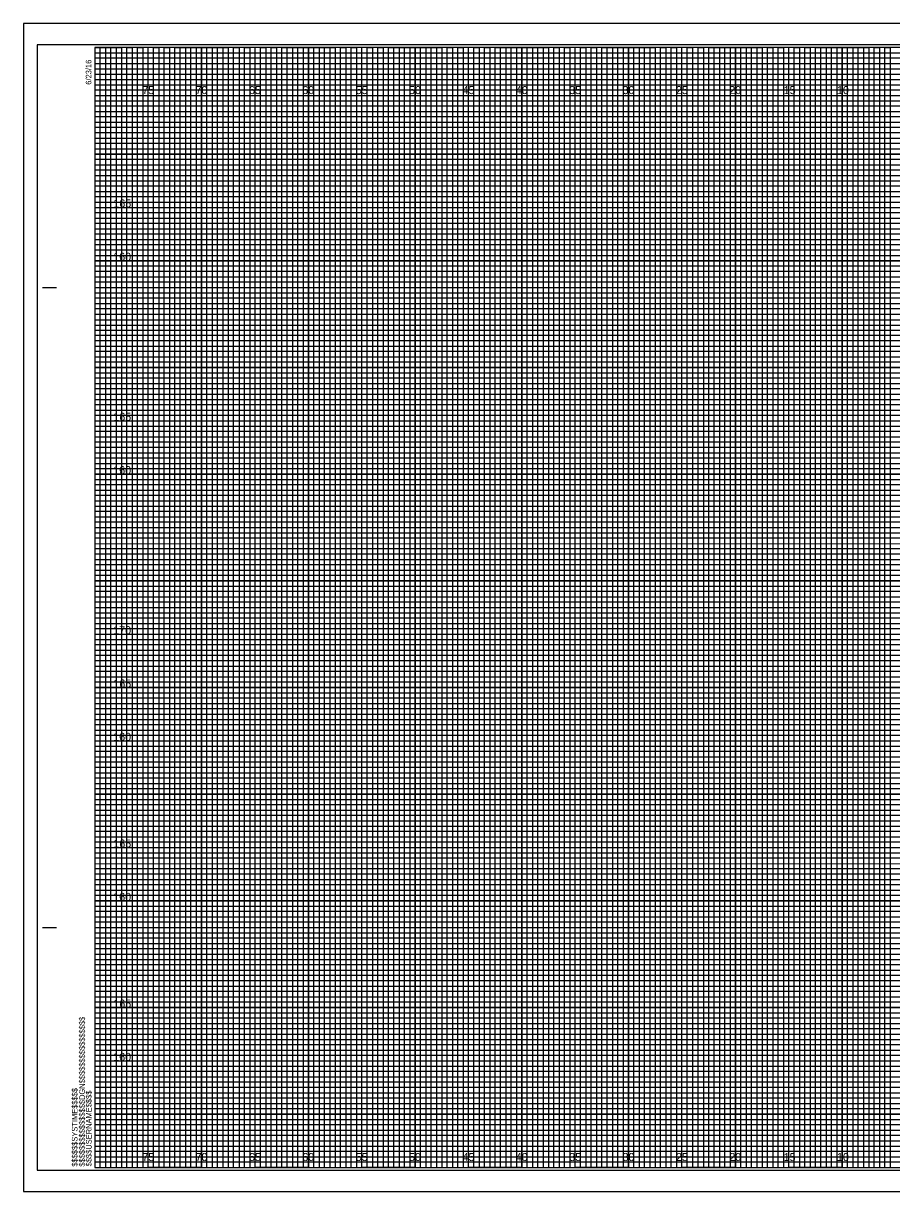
# Model space of a CAD drawing. Extents: x -7 to 162, y -2 to 107.
# Drawn here: x -6.7 to 74.6, y -2.3 to 107.3 of the extents above; entities that cross this region are included whole.
import ezdxf

# ---------------------------------------------------------------- set-up
doc = ezdxf.new("R2010")
doc.units = 0
for name, color, linetype in [('Exist CMT Pavement', 7, 'Continuous'), ('Prop CMT Pvmt Course 1 Wedge', 7, 'Continuous'), ('Prop CMT Pvmt Course 2 Wedge', 7, 'Continuous'), ('Prop CMT Pvmt Course 3 Wedge', 7, 'Continuous'), ('Prop CMT Pvmt Wedge Surface 1', 7, 'Continuous'), ('Prop CMT Pvmt Wedge Surface 2', 7, 'Continuous'), ('Prop XS Ditch Standard Text', 7, 'Continuous'), ('Prop XS Earthwork Shape', 7, 'Continuous'), ('Prop XS Hydro Elevations', 7, 'Continuous'), ('Prop XS SE Text', 7, 'Continuous'), ('Prop XS Side Slope Text', 7, 'Continuous')]:
    doc.layers.add(name, color=color, linetype=linetype)

msp = doc.modelspace()

# ---------------------------------------------------------------- linework, layer by layer
at = {"layer": 'Exist CMT Pavement'}
for p, q in [((0, 104.5), (130, 104.5)), ((130, 103.99), (0, 103.99)), ((0, 103.99), (0, 103.5)), ((0, 103.5), (130, 103.5)), ((130, 102.95), (0, 102.95)), ((0, 102.95), (0, 102)), ((0, 102), (160, 102))]:
    msp.add_line(p, q, dxfattribs=at)
for points in [[(0, 101.5), (135, 101.5), (160, 101.5), (160, 101), (0, 101)], [(0, 100.5), (160, 100.5), (160, 99.5), (0, 99.5)], [(0, 99), (160, 99), (160, 98.5), (0, 98.49)], [(0, 98), (160, 98), (160, 97), (0, 97)], [(0, 96.5), (160, 96.5), (160, 96), (0, 96)], [(0, 95.5), (160, 95.5), (160, 94.5), (0, 94.5)], [(0, 94), (160, 94), (160, 93.5), (0, 93.5)], [(0, 93), (160, 93), (160, 92), (0, 92)], [(0, 91.5), (160, 91.5), (160, 91), (0, 91)], [(0, 90.5), (160, 90.5), (160, 89.5), (0, 89.5)], [(0, 89), (160, 89), (160, 88.5), (0, 88.5)], [(0, 88), (160, 88), (160, 86.98), (160, 86.5), (160, 86), (0, 86)], [(0, 87), (160, 87), (160, 86.5), (0, 86.5)], [(0, 85.5), (160, 85.5), (160, 84.5), (0, 84.52)], [(0, 84.52), (160, 84.5), (160, 84), (0, 84)], [(0, 83.5), (160, 83.5), (160, 83), (0, 83)], [(0, 82), (160, 82), (160, 81.5), (0, 81.5)], [(0, 81), (160, 81), (160, 80.5), (0, 80.5)], [(-0.04, 79.45), (160, 79.45), (160, 78.94), (-0.04, 78.94)], [(0, 78.5), (160, 78.5), (160, 78), (0, 78)], [(0, 77), (160, 77), (160, 76.5), (0, 76.5)], [(0, 76), (160, 76), (160, 75.5), (0, 75.5)], [(0, 74.5), (160, 74.5), (160, 74), (0, 74)], [(0, 73.5), (160, 73.5), (160, 73), (0, 73)], [(0, 72), (160, 72), (160, 71.5), (0, 71.5)], [(0, 71), (160, 71), (160, 70.5), (0, 70.5)], [(0, 69.5), (160, 69.5), (160, 68.99), (0, 69)], [(0, 68.5), (160, 68.5), (160, 68), (0, 68)], [(0, 67), (160, 67), (160, 66.5), (0, 66.5)], [(0, 66), (160, 66), (160, 65.5), (0, 65.5)], [(0, 64.5), (160, 64.5), (160, 64), (0, 64)], [(0, 63.5), (160, 63.5), (160, 63), (0, 63)], [(0, 62), (160, 62), (160, 61.5), (0, 61.5)], [(0, 61), (160, 61), (160, 60.5), (0, 60.5)], [(0, 59.5), (160, 59.5), (160, 59), (0, 59)], [(0, 58.5), (160.03, 58.45), (160, 58), (0, 58)], [(0, 57), (160, 57), (160, 56.5), (0, 56.5)], [(0, 56), (160, 56), (160, 55.5), (0, 55.5)], [(0, 54.5), (160, 54.5), (160, 54), (0, 54)], [(0, 53.5), (160, 53.5), (160, 53), (0, 53)], [(0, 52), (160, 52), (160, 51.5), (0, 51.5)], [(0, 51), (160, 51), (160, 50.5), (0, 50.5)], [(0, 49.5), (160, 49.5), (160, 49), (0, 49)], [(0, 48.5), (160, 48.5), (160, 48), (0, 48)], [(0, 47), (160, 47), (160, 46.5), (0, 46.5)], [(0, 46), (160, 46), (160, 45.5), (0, 45.5)], [(0, 44.5), (160, 44.5), (160, 44), (0, 44)], [(0, 43.5), (160, 43.5), (160, 43), (0, 43)], [(0, 42), (160, 42), (160, 41.5), (0, 41.5)], [(0, 41), (160, 41), (160, 40.5), (0, 40.5)], [(0, 39.5), (160, 39.5), (160, 38.99), (0, 39)], [(0, 38.5), (160, 38.5), (160, 38), (0, 38)], [(0, 37), (160, 37), (160, 36.5), (0, 36.5)], [(0, 36), (160, 36), (160, 35.5), (0, 35.5)], [(0, 34.5), (160, 34.5), (160, 34), (0, 34)], [(0, 33.5), (160, 33.5), (160, 33), (0, 33)], [(0, 32), (160, 32), (160, 31.5), (0, 31.5)], [(0, 31), (160, 31), (160, 30.5), (0, 30.5)], [(0, 29.5), (160, 29.5), (160, 29), (0, 29)], [(0, 28.5), (160.03, 28.46), (160, 28), (0, 28)], [(0, 27), (160, 27), (160, 26.5), (0, 26.5)], [(0, 26), (160, 26), (160, 25.5), (0, 25.5)], [(0, 24.5), (160, 24.5), (160, 24), (0, 24)], [(0, 23.5), (160, 23.5), (160, 23), (0, 23)], [(0, 22), (160, 22), (160, 21.5), (0, 21.5)], [(0, 21), (160, 21), (160, 20.5), (0, 20.5)], [(0, 19.5), (160, 19.5), (160, 19), (0, 19)], [(0, 18.5), (160, 18.5), (160, 18), (0, 18)], [(0, 17), (160, 17), (160, 16.5), (0, 16.5)], [(0, 16), (160, 16), (160, 15.5), (0, 15.5)], [(0, 14.5), (160, 14.5), (160, 14), (0, 14)], [(0, 13.5), (160, 13.5), (160, 13), (0, 13)], [(0, 12), (160, 12), (160, 11.5), (0, 11.5)], [(0, 11), (160, 11), (160, 10.5), (0, 10.5)], [(0, 9.5), (160, 9.5), (160, 9), (0, 9)], [(0, 8.5), (160, 8.5), (160, 8), (0, 8)], [(0, 7), (160, 7), (160, 6.5), (0, 6.5)], [(0, 6), (160, 6), (160, 5.5), (0, 5.5)], [(0, 4.5), (160, 4.5), (160, 4), (0, 4)], [(0, 3.5), (160, 3.5), (160, 3), (0, 3)], [(0, 2), (160, 2), (160, 1.5), (0, 1.5)], [(0, 1), (160, 1), (160, 0.5), (0, 0.5)]]:
    msp.add_lwpolyline(points, dxfattribs=at)
at = {"layer": 'Prop CMT Pvmt Course 2 Wedge'}
for p, q in [((5, 105), (0, 105)), ((5, 0), (5, 105)), ((15, 105), (10, 105)), ((10, 105), (10, 0)), ((15, 0), (15, 105)), ((25, 105), (20, 105)), ((20, 105), (20, 0)), ((25, 0), (25, 105)), ((35, 105), (30, 105)), ((30, 105), (30, 0)), ((35, 0), (35, 105)), ((45, 105), (40, 105)), ((40, 105), (40, 0)), ((45, 0), (45, 105)), ((55, 105), (50, 105)), ((50, 105), (50, 0)), ((55, 0), (55, 105)), ((65, 105), (60, 105)), ((60, 105), (60, 0)), ((65, 0), (65, 105)), ((75, 105), (70, 105)), ((70, 105), (70, 0)), ((10, 0), (5, 0)), ((20, 0), (15, 0)), ((30, 0), (25, 0)), ((40, 0), (35, 0)), ((50, 0), (45, 0)), ((60, 0), (55, 0)), ((70, 0), (65, 0))]:
    msp.add_line(p, q, dxfattribs=at)
for points in [[(0, 100), (160, 100), (160, 95), (0, 95)], [(0, 90), (160, 90), (160, 85), (0, 85)], [(0, 80), (160, 80), (160, 75), (0, 75)], [(0, 70), (160, 70), (160, 65), (0, 65)], [(0, 60), (160, 60), (160, 55), (0, 55)], [(0, 50), (160, 50), (160, 45), (0, 45)], [(0, 40), (160, 40), (160, 35), (0, 35)], [(0, 30), (160, 30), (160, 25), (0, 25)], [(0, 20), (160, 20), (160, 15), (0, 15)], [(0, 10), (160, 10), (160, 5), (0, 5)]]:
    msp.add_lwpolyline(points, dxfattribs=at)
at = {"layer": 'Prop CMT Pvmt Course 3 Wedge'}
for points in [[(0, 105), (2.5, 105), (2.5, 0), (7.5, 0), (7.5, 105), (12.5, 105), (12.5, 0), (17.5, 0), (17.5, 105), (22.5, 105), (22.5, 0), (27.5, 0), (27.5, 105), (32.5, 105), (32.5, 0), (37.5, 0), (37.5, 105), (42.5, 105), (42.5, 0), (47.5, 0), (47.5, 105), (52.5, 105), (52.5, 0), (57.5, 0), (57.5, 105), (62.5, 105), (62.5, 0), (67.5, 0), (67.5, 105), (72.5, 105), (72.5, 0), (77.5, 0)], [(0, 102.5), (137.5, 102.5)], [(0, 92.5), (160, 92.5), (160, 97.5), (0, 97.5)], [(0, 82.5), (160, 82.5), (160, 87.5), (0, 87.5)], [(0, 72.5), (160, 72.5), (160, 77.5), (0, 77.5)], [(0, 62.5), (160, 62.5), (160, 67.5), (0, 67.5)], [(0, 52.5), (160, 52.5), (160, 57.5), (0, 57.5)], [(0, 42.5), (160, 42.5), (160, 47.5), (0, 47.5)], [(0, 32.5), (160, 32.5), (160, 37.5), (0, 37.5)], [(0, 22.5), (160, 22.5), (160, 27.5), (0, 27.5)], [(0, 12.5), (160, 12.5), (160, 17.5), (0, 17.5)], [(0, 2.5), (160, 2.5), (160, 7.5), (0, 7.5)]]:
    msp.add_lwpolyline(points, dxfattribs=at)
at = {"layer": 'Prop CMT Pvmt Wedge Surface 1'}
for p, q in [((-4.9, 82.5), (-3.65, 82.5)), ((-4.85, 82.5), (-3.6, 82.5)), ((-4.9, 22.5), (-3.65, 22.5)), ((-4.85, 22.5), (-3.6, 22.5)), ((0, 0), (0, 0)), ((0, 0), (0, 0)), ((0, 0), (0, 0)), ((0, 0), (0, 0)), ((0, 0), (0, 0)), ((0, 0), (0, 0)), ((0, 0), (0, 0))]:
    msp.add_line(p, q, dxfattribs=at)
msp.add_lwpolyline([(160, 105), (0, 105), (0, 0), (160, 0)], close=True, dxfattribs=at)
at = {"layer": 'Prop CMT Pvmt Wedge Surface 2'}
for points in [[(0, 0), (0.5, 0), (0.5, 105), (1, 105), (1, 0)], [(1, 0), (1.5, 0), (1.5, 105), (2, 105), (2, 0)], [(2.5, 0), (3, 0), (3, 105), (3.5, 105), (3.5, 0)], [(3.5, 0), (4, 0), (4, 105), (4.5, 105), (4.5, 0)], [(5, 0), (5.5, 0), (5.5, 105), (6, 105), (6, 0)], [(6, 0), (6.5, 0), (6.5, 105), (7, 105), (7, 0)], [(7.5, 0), (8, 0), (8, 105), (8.5, 105), (8.5, 0)], [(8.5, 0), (9, 0), (9, 105), (9.5, 105), (9.5, 0)], [(10, 0), (10.5, 0), (10.5, 105), (11, 105), (11, 0)], [(11, 0), (11.5, 0), (11.5, 105), (12, 105), (12, 0)], [(12.5, 0), (13, 0), (13, 105), (13.5, 105), (13.5, 0)], [(13.5, 0), (14, 0), (14, 105), (14.5, 105), (14.5, 0)], [(15, 0), (15.5, 0), (15.5, 105), (16, 105), (16, 0)], [(16, 0), (16.5, 0), (16.5, 105), (17, 105), (17, 0)], [(17.5, 0), (18, 0), (18, 105), (18.5, 105), (18.5, 0)], [(18.5, 0), (19, 0), (19, 105), (19.5, 105), (19.5, 0)], [(20, 0), (20.5, 0), (20.5, 105), (21, 105), (21, 0)], [(21, 0), (21.5, 0), (21.5, 105), (22, 105), (22, 0)], [(22.5, 0), (23, 0), (23, 105), (23.5, 105), (23.5, 0)], [(23.5, 0), (24, 0), (24, 105), (24.5, 105), (24.5, 0)], [(25, 0), (25.5, 0), (25.5, 105), (26, 105), (26, 0)], [(26, 0), (26.5, 0), (26.5, 105), (27, 105), (27, 0)], [(27.5, 0), (28, 0), (28, 105), (28.5, 105), (28.5, 0)], [(28.5, 0), (29, 0), (29, 105), (29.5, 105), (29.5, 0)], [(30, 0), (30.5, 0), (30.5, 105), (31, 105), (31, 0)], [(31, 0), (31.5, 0), (31.5, 105), (32, 105), (32, 0)], [(32.5, 0), (33, 0), (33, 105), (33.5, 105), (33.5, 0)], [(33.5, 0), (34, 0), (34, 105), (34.5, 105), (34.5, 0)], [(35, 0), (35.5, 0), (35.5, 105), (36, 105), (36, 0)], [(36, 0), (36.5, 0), (36.5, 105), (37, 105), (37, 0)], [(37.5, 0), (38, 0), (38, 105), (38.5, 105), (38.5, 0)], [(38.5, 0), (39, 0), (39, 105), (39.5, 105), (39.5, 0)], [(40, 0), (40.5, 0), (40.5, 105), (41, 105), (41, 0)], [(41, 0), (41.5, 0), (41.5, 105), (42, 105), (42, 0)], [(42.5, 0), (43, 0), (43, 105), (43.5, 105), (43.5, 0)], [(43.5, 0), (44, 0), (44, 105), (44.5, 105), (44.5, 0)], [(45, 0), (45.5, 0), (45.5, 105), (46, 105), (46, 0)], [(46, 0), (46.5, 0), (46.5, 105), (47, 105), (47, 0)], [(47.5, 0), (48, 0), (48, 105), (48.5, 105), (48.5, 0)], [(48.5, 0), (49, 0), (49, 105), (49.5, 105), (49.5, 0)], [(50, 0), (50.5, 0), (50.5, 105), (51, 105), (51, 0)], [(51, 0), (51.5, 0), (51.5, 105), (52, 105), (52, 0)], [(52.5, 0), (53, 0), (53, 105), (53.5, 105), (53.5, 0)], [(53.5, 0), (54, 0), (54, 105), (54.5, 105), (54.5, 0)], [(55, 0), (55.5, 0), (55.5, 105), (56, 105), (56, 0)], [(56, 0), (56.5, 0), (56.5, 105), (57, 105), (57, 0)], [(57.5, 0), (58, 0), (58, 105), (58.5, 105), (58.5, 0)], [(58.5, 0), (59, 0), (59, 105), (59.5, 105), (59.5, 0)], [(60, 0), (60.5, 0), (60.5, 105), (61, 105), (61, 0)], [(61, 0), (61.5, 0), (61.5, 105), (62, 105), (62, 0)], [(62.5, 0), (63, 0), (63, 105), (63.5, 105), (63.5, 0)], [(63.5, 0), (64, 0), (64, 105), (64.5, 105), (64.5, 0)], [(65, 0), (65.5, 0), (65.5, 105), (66, 105), (66, 0)], [(66, 0), (66.5, 0), (66.5, 105), (67, 105), (67, 0)], [(67.5, 0), (68, 0), (68, 105), (68.5, 105), (68.5, 0)], [(68.5, 0), (69, 0), (69, 105), (69.5, 105), (69.5, 0)], [(70, 0), (70.5, 0), (70.5, 105), (71, 105), (71, 0)], [(71, 0), (71.5, 0), (71.5, 105), (72, 105), (72, 0)], [(72.5, 0), (73, 0), (73, 105), (73.5, 105), (73.5, 0)], [(73.5, 0), (74, 0), (74, 105), (74.5, 105), (74.5, 0)]]:
    msp.add_lwpolyline(points, dxfattribs=at)
at = {"layer": 'Prop XS Ditch Standard Text'}
for p, q in [((161.65, 107.25), (-6.7, 107.25)), ((-6.7, 107.25), (-6.7, -2.25)), ((-6.7, -2.25), (161.65, -2.25))]:
    msp.add_line(p, q, dxfattribs=at)
at = {"layer": 'Prop XS Hydro Elevations'}
for p, q in [((5, 0), (5, 105)), ((10, 0), (10, 105)), ((15, 0), (15, 105)), ((20, 0), (20, 105)), ((25, 0), (25, 105)), ((30, 0), (30, 105)), ((35, 0), (35, 105)), ((40, 0), (40, 105)), ((45, 0), (45, 105)), ((50, 0), (50, 105)), ((55, 0), (55, 105)), ((60, 0), (60, 105)), ((65, 0), (65, 105)), ((70, 0), (70, 105)), ((0, 100), (160, 100)), ((0, 95), (160, 95)), ((0, 90), (160, 90)), ((0, 85), (160, 85)), ((0, 80), (160, 80)), ((0, 75), (160, 75)), ((0, 70), (160, 70)), ((0, 65), (160, 65)), ((0, 60), (160, 60)), ((0, 55), (160, 55)), ((0, 50), (160, 50)), ((0, 45), (160, 45)), ((0, 40), (160, 40)), ((0, 35), (160, 35)), ((0, 30), (160, 30)), ((0, 25), (160, 25)), ((0, 20), (160, 20)), ((0, 15), (160, 15)), ((0, 10), (160, 10)), ((0, 5), (160, 5))]:
    msp.add_line(p, q, dxfattribs=at)
at = {"layer": 'Prop XS SE Text'}
msp.add_lwpolyline([(-6.7, -2.25), (161.65, -2.25), (161.65, 107.25), (-6.7, 107.25)], close=True, dxfattribs=at)
at = {"layer": 'Prop XS Side Slope Text'}
msp.add_lwpolyline([(-5.4, -0.25), (161.2, -0.25), (161.2, 105.25), (-5.4, 105.25)], close=True, dxfattribs=at)

# ---------------------------------------------------------------- texts
at = {"layer": 'Prop CMT Pvmt Course 1 Wedge'}
for s, p in [('75', (4.44, 100.62)), ('70', (9.43, 100.62)), ('65', (14.44, 100.62)), ('60', (19.43, 100.62)), ('55', (24.44, 100.62)), ('50', (29.43, 100.62)), ('45', (34.44, 100.62)), ('40', (39.43, 100.62)), ('35', (44.44, 100.62)), ('30', (49.43, 100.62)), ('25', (54.44, 100.62)), ('20', (59.43, 100.62)), ('15', (64.53, 100.62)), ('10', (69.52, 100.62)), ('75', (4.44, 0.62)), ('70', (9.43, 0.62)), ('65', (14.44, 0.62)), ('60', (19.43, 0.62)), ('55', (24.44, 0.62)), ('50', (29.43, 0.62)), ('45', (34.44, 0.62)), ('40', (39.43, 0.62)), ('35', (44.44, 0.62)), ('30', (49.43, 0.62)), ('25', (54.44, 0.62)), ('20', (59.43, 0.62)), ('15', (64.53, 0.62)), ('10', (69.52, 0.62))]:
    msp.add_text(s, height=0.75, dxfattribs=at).set_placement(p)
at = {"layer": 'Prop CMT Pvmt Wedge Surface 1'}
for s, p in [('6/23/16', (-0.33, 101.5)), ('$$$$$$$$$$$$$$$$DGN$$$$$$$$$$$$$$$$', (-0.94, 0.09)), ('$$$$$$SYSTIME$$$$$', (-1.63, 0.09)), ('$$$$USERNAME$$$$', (-0.31, 0.12))]:
    msp.add_text(s, height=0.525, rotation=90, dxfattribs=at).set_placement(p)
at = {"layer": 'Prop XS Earthwork Shape'}
for s, p in [('165', (1.73, 90)), ('160', (1.72, 85)), ('165', (1.73, 70)), ('160', (1.72, 65)), ('170', (1.72, 50)), ('165', (1.73, 45)), ('160', (1.72, 40)), ('165', (1.73, 30)), ('160', (1.72, 25)), ('165', (1.73, 15)), ('160', (1.72, 10))]:
    msp.add_text(s, height=0.75, dxfattribs=at).set_placement(p)

doc.saveas('drawing.dxf')
